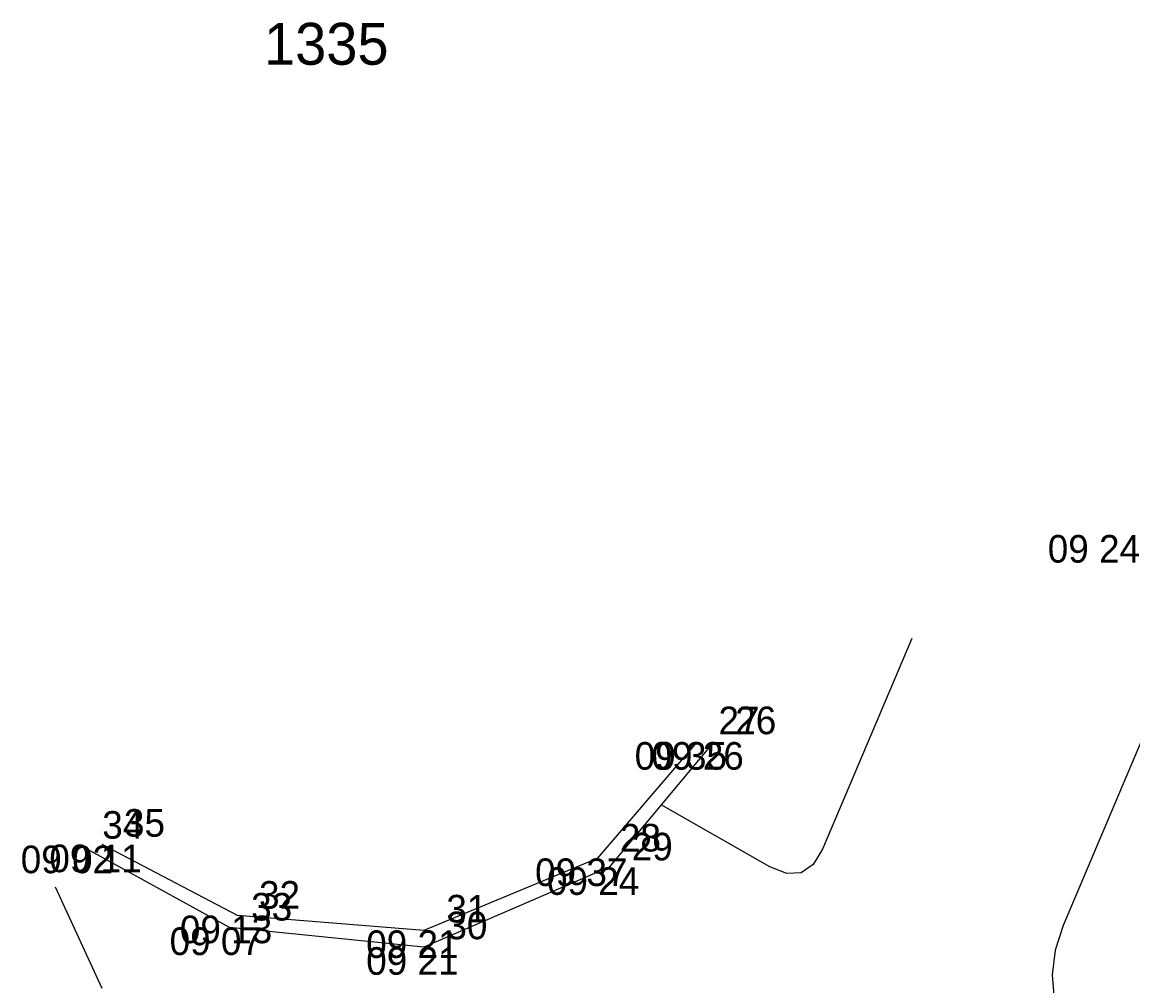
# Model space of a CAD drawing. Extents: x -711234 to -710007, y -1026313 to -1025448.
# Drawn here: x -711004.27 to -710993.01, y -1025868.34 to -1025858.57 of the extents above; entities that cross this region are included whole.
import ezdxf

# ---------------------------------------------------------------- set-up
doc = ezdxf.new("R2010")
doc.units = 0
for name, color, linetype in [('Ex_Major Contours', 7, 'Continuous'), ('Ex_Minor Contours', 7, 'Continuous'), ('Z_body', 7, 'Continuous'), ('Z_body_cisla', 7, 'Continuous'), ('Z_body_vysky_redukovane', 7, 'Continuous'), ('Z_katastr_cisla_pozemkova', 7, 'Continuous'), ('Z_komunikace', 7, 'Continuous'), ('Z_obruba', 7, 'Continuous')]:
    doc.layers.add(name, color=color, linetype=linetype)

# ---------------------------------------------------------------- blocks, each defined once
blk = doc.blocks.new('POINT_DISPLAY')
blk.add_line((0, 0), (0, 0))

msp = doc.modelspace()

# ---------------------------------------------------------------- linework, layer by layer
at = {"layer": 'Ex_Major Contours'}
msp.add_lwpolyline([(-711003.938, -1025867.338), (-711003.464, -1025868.366)], dxfattribs=at)
at = {"layer": 'Ex_Minor Contours'}
for points in [[(-710995.25, -1025864.82), (-710996.155, -1025866.955), (-710996.25, -1025867.113), (-710996.371, -1025867.195), (-710996.516, -1025867.203), (-710996.688, -1025867.135), (-710997.79, -1025866.505)], [(-710992.704, -1025865.345), (-710993.715, -1025867.732), (-710993.796, -1025867.981), (-710993.825, -1025868.232), (-710993.804, -1025868.483), (-710993.732, -1025868.735), (-710993.272, -1025869.926), (-710993.224, -1025870.088), (-710993.206, -1025870.251), (-710993.217, -1025870.415), (-710993.259, -1025870.579), (-710993.588, -1025871.548), (-710993.589, -1025871.556), (-710993.588, -1025871.564), (-710993.583, -1025871.569), (-710993.575, -1025871.573), (-710993.537, -1025871.586), (-710993.528, -1025871.588), (-710993.518, -1025871.589), (-710993.508, -1025871.59), (-710993.498, -1025871.588), (-710991.797, -1025871.299)]]:
    msp.add_lwpolyline(points, dxfattribs=at)
at = {"layer": 'Z_komunikace'}
for p, q in [((-710997.26, -1025865.87), (-710998.32, -1025867.14)), ((-711002.17, -1025867.75), (-711003.68, -1025866.92)), ((-710998.32, -1025867.14), (-711000.2, -1025867.95)), ((-711000.2, -1025867.95), (-711002.17, -1025867.75))]:
    msp.add_line(p, q, dxfattribs=at)
at = {"layer": 'Z_obruba'}
for p, q in [((-710997.43, -1025865.87), (-710998.44, -1025867.05)), ((-711002.09, -1025867.63), (-711003.46, -1025866.91)), ((-710998.44, -1025867.05), (-711000.2, -1025867.78)), ((-711000.2, -1025867.78), (-711002.09, -1025867.63))]:
    msp.add_line(p, q, dxfattribs=at)

# ---------------------------------------------------------------- block references
at = {"layer": 'Z_body'}
for p in [(-710993.24, -1025863.77), (-710997.43, -1025865.87), (-710997.26, -1025865.87), (-711003.68, -1025866.92), (-711003.46, -1025866.91), (-710998.44, -1025867.05), (-710998.32, -1025867.14), (-711002.09, -1025867.63), (-711002.17, -1025867.75), (-711000.2, -1025867.78), (-711000.2, -1025867.95)]:
    msp.add_blockref('POINT_DISPLAY', p, dxfattribs=at)

# ---------------------------------------------------------------- texts
at = {"layer": 'Z_body_cisla'}
for s, p in [('27', (-710997.21, -1025865.79)), ('26', (-710997.04, -1025865.79)), ('34', (-711003.46, -1025866.85)), ('35', (-711003.24, -1025866.83)), ('28', (-710998.21, -1025866.98)), ('29', (-710998.09, -1025867.07)), ('32', (-711001.87, -1025867.56)), ('33', (-711001.95, -1025867.68)), ('31', (-710999.97, -1025867.7)), ('30', (-710999.97, -1025867.87))]:
    msp.add_text(s, height=0.28, dxfattribs=at).set_placement(p)
at = {"layer": 'Z_body_vysky_redukovane'}
for s, p in [('09 24', (-710993.87, -1025864.05)), ('09 35', (-710998.06, -1025866.15)), ('09 26', (-710997.89, -1025866.15)), ('09 02', (-711004.287, -1025867.2)), ('09 11', (-711003.997, -1025867.19)), ('09 37', (-710999.07, -1025867.33)), ('09 24', (-710998.95, -1025867.42)), ('09 13', (-711002.673, -1025867.91)), ('09 07', (-711002.777, -1025868.03)), ('09 21', (-711000.783, -1025868.06)), ('09 21', (-711000.783, -1025868.23))]:
    msp.add_text(s, height=0.28, dxfattribs=at).set_placement(p)
at = {"layer": 'Z_katastr_cisla_pozemkova'}
msp.add_text('1335', height=0.425, dxfattribs=at).set_placement((-711001.82, -1025859))

doc.saveas('drawing.dxf')
